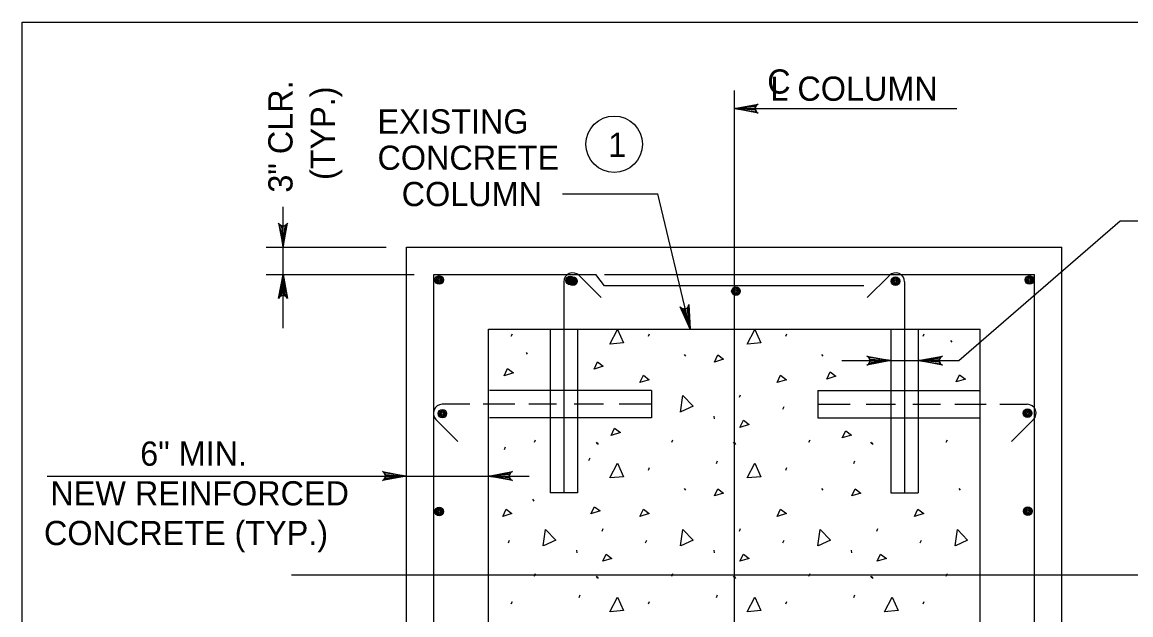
# Model space of a CAD drawing. Extents: x 646165 to 651486, y 296916 to 299292.
# Drawn here: x 650670.6 to 650808, y 298015.8 to 298089.3 of the extents above; entities that cross this region are included whole.
import ezdxf

# ---------------------------------------------------------------- set-up
doc = ezdxf.new("R2010")
doc.units = 0
for name, color, linetype in [('2', 7, 'Continuous'), ('50', 7, 'Continuous'), ('51', 7, 'Continuous'), ('52', 7, 'Continuous'), ('53', 7, 'Continuous'), ('54', 7, 'Continuous'), ('56', 7, 'Continuous')]:
    doc.layers.add(name, color=color, linetype=linetype)

msp = doc.modelspace()

# ---------------------------------------------------------------- linework, layer by layer
at = {"layer": '2'}
for p, q in [((650670.59, 297525.25), (650670.59, 298089.25)), ((650670.59, 298089.25), (651456.59, 298089.25))]:
    msp.add_line(p, q, dxfattribs=at)
at = {"layer": '50'}
for p, q in [((650758.84, 298080.79), (650758.84, 297974.65)), ((650703.98, 298020.74), (650812.55, 298020.74))]:
    msp.add_line(p, q, dxfattribs=at)
at = {"layer": '51'}
for p, q in [((650718.21, 297980.12), (650718.21, 298061.37)), ((650718.21, 298061.37), (650799.47, 298061.37)), ((650799.47, 297980.12), (650799.47, 298061.37)), ((650728.37, 297990.27), (650728.37, 298051.21)), ((650728.37, 298051.21), (650789.31, 298051.21)), ((650736.02, 298051.21), (650736.02, 298030.9)), ((650739.41, 298051.21), (650739.41, 298030.9)), ((650778.27, 298051.21), (650778.27, 298030.9)), ((650781.66, 298051.21), (650781.66, 298030.9)), ((650789.31, 297990.27), (650789.31, 298051.21)), ((650748.61, 298043.58), (650728.5, 298043.58)), ((650748.61, 298043.58), (650748.61, 298040.2)), ((650769.2, 298043.58), (650789.31, 298043.58)), ((650769.2, 298043.58), (650769.2, 298040.2)), ((650748.61, 298040.2), (650728.5, 298040.2)), ((650769.2, 298040.2), (650789.31, 298040.2)), ((650739.41, 298030.9), (650736.02, 298030.9)), ((650778.27, 298030.9), (650781.66, 298030.9))]:
    msp.add_line(p, q, dxfattribs=at)
at = {"layer": '52'}
for p, q in [((650758.84, 298078.54), (650786.45, 298078.54)), ((650737.55, 298067.96), (650749.37, 298067.96)), ((650753.37, 298051.21), (650749.37, 298067.96)), ((650702.93, 298051.32), (650702.93, 298066.38)), ((650786.68, 298047.3), (650806.7, 298064.64)), ((650806.7, 298064.64), (650812.07, 298064.64)), ((650700.85, 298061.37), (650715.69, 298061.37)), ((650700.85, 298057.99), (650719.17, 298057.99)), ((650772.17, 298047.3), (650786.68, 298047.3)), ((650673.7, 298032.99), (650733.41, 298032.99))]:
    msp.add_line(p, q, dxfattribs=at)
for points in [[(650758.84, 298078.54), (650761.82, 298079.1), (650761.59, 298078.94), (650761.47, 298078.74), (650761.44, 298078.54), (650761.47, 298078.34), (650761.59, 298078.14), (650761.82, 298077.98), (650758.84, 298078.54), (650761.59, 298078.14), (650761.47, 298078.34), (650758.84, 298078.54), (650761.44, 298078.54), (650761.47, 298078.74), (650758.84, 298078.54), (650761.59, 298078.94)], [(650702.93, 298061.37), (650703.49, 298064.35), (650703.33, 298064.12), (650703.13, 298064.01), (650702.93, 298063.97), (650702.73, 298064.01), (650702.53, 298064.12), (650702.37, 298064.35), (650702.93, 298061.37), (650702.53, 298064.12), (650702.73, 298064.01), (650702.93, 298061.37), (650702.93, 298063.97), (650703.13, 298064.01), (650702.93, 298061.37), (650703.33, 298064.12)], [(650702.93, 298057.99), (650703.49, 298055), (650703.33, 298055.23), (650703.13, 298055.35), (650702.93, 298055.39), (650702.73, 298055.35), (650702.53, 298055.23), (650702.37, 298055), (650702.93, 298057.99), (650702.53, 298055.23), (650702.73, 298055.35), (650702.93, 298057.99), (650702.93, 298055.39), (650703.13, 298055.35), (650702.93, 298057.99), (650703.33, 298055.23)], [(650753.37, 298051.21), (650752.13, 298053.99), (650752.34, 298053.8), (650752.56, 298053.73), (650752.77, 298053.74), (650752.95, 298053.82), (650753.12, 298053.98), (650753.22, 298054.25), (650753.37, 298051.21), (650753.12, 298053.98), (650752.95, 298053.82), (650753.37, 298051.21), (650752.77, 298053.74), (650752.56, 298053.73), (650753.37, 298051.21), (650752.34, 298053.8)], [(650778.27, 298047.3), (650775.29, 298046.74), (650775.52, 298046.9), (650775.64, 298047.1), (650775.67, 298047.3), (650775.64, 298047.5), (650775.52, 298047.7), (650775.29, 298047.86), (650778.27, 298047.3), (650775.52, 298047.7), (650775.64, 298047.5), (650778.27, 298047.3), (650775.67, 298047.3), (650775.64, 298047.1), (650778.27, 298047.3), (650775.52, 298046.9)], [(650781.66, 298047.3), (650784.64, 298047.86), (650784.41, 298047.7), (650784.29, 298047.5), (650784.26, 298047.3), (650784.29, 298047.1), (650784.41, 298046.9), (650784.64, 298046.74), (650781.66, 298047.3), (650784.41, 298046.9), (650784.29, 298047.1), (650781.66, 298047.3), (650784.26, 298047.3), (650784.29, 298047.5), (650781.66, 298047.3), (650784.41, 298047.7)], [(650718.21, 298032.99), (650715.23, 298032.43), (650715.46, 298032.59), (650715.58, 298032.79), (650715.61, 298032.99), (650715.58, 298033.19), (650715.46, 298033.39), (650715.23, 298033.55), (650718.21, 298032.99), (650715.46, 298033.39), (650715.58, 298033.19), (650718.21, 298032.99), (650715.61, 298032.99), (650715.58, 298032.79), (650718.21, 298032.99), (650715.46, 298032.59)], [(650728.37, 298032.99), (650731.35, 298033.55), (650731.12, 298033.39), (650731, 298033.19), (650730.97, 298032.99), (650731, 298032.79), (650731.12, 298032.59), (650731.35, 298032.43), (650728.37, 298032.99), (650731.12, 298032.59), (650731, 298032.79), (650728.37, 298032.99), (650730.97, 298032.99), (650731, 298033.19), (650728.37, 298032.99), (650731.12, 298033.39)]]:
    msp.add_lwpolyline(points, dxfattribs=at)
msp.add_circle((650743.96, 298074.12), 3.5, dxfattribs=at)
at = {"layer": '54'}
for p, q in [((650721.6, 297983.5), (650721.6, 298057.99)), ((650721.6, 298057.99), (650741.69, 298057.99)), ((650737.71, 298057.06), (650737.71, 298030.9)), ((650739.61, 298057.85), (650742.34, 298055.12)), ((650742.76, 298056.56), (650741.69, 298057.99)), ((650742.76, 298057.99), (650796.08, 298057.99)), ((650778.07, 298057.85), (650775.34, 298055.12)), ((650779.96, 298057.06), (650779.96, 298030.9)), ((650796.08, 297983.5), (650796.08, 298057.99)), ((650774.92, 298056.56), (650742.76, 298056.56)), ((650726.06, 298041.89), (650722.66, 298041.89)), ((650731.64, 298041.89), (650727.73, 298041.89)), ((650736.81, 298041.89), (650733.39, 298041.89)), ((650742.63, 298041.89), (650738.99, 298041.89)), ((650748.61, 298041.89), (650744.6, 298041.89)), ((650769.2, 298041.89), (650773.21, 298041.89)), ((650775.18, 298041.89), (650778.82, 298041.89)), ((650781, 298041.89), (650784.42, 298041.89)), ((650786.17, 298041.89), (650790.08, 298041.89)), ((650791.75, 298041.89), (650795.15, 298041.89)), ((650721.88, 298039.99), (650724.6, 298037.27)), ((650795.93, 298039.99), (650793.21, 298037.27))]:
    msp.add_line(p, q, dxfattribs=at)
for centre, radius in [((650722.27, 298057.3), 0.533), ((650722.27, 298057.3), 0.4), ((650722.27, 298057.3), 0.267), ((650722.27, 298057.3), 0.133), ((650738.52, 298057.24), 0.533), ((650738.52, 298057.24), 0.4), ((650738.52, 298057.24), 0.267), ((650738.86, 298057.16), 0.533), ((650738.52, 298057.24), 0.133), ((650738.86, 298057.16), 0.4), ((650738.86, 298057.16), 0.267), ((650738.86, 298057.16), 0.133), ((650778.82, 298057.16), 0.533), ((650778.82, 298057.16), 0.4), ((650778.82, 298057.16), 0.267), ((650778.82, 298057.16), 0.133), ((650795.43, 298057.3), 0.533), ((650795.43, 298057.3), 0.4), ((650795.43, 298057.3), 0.267), ((650795.43, 298057.3), 0.133), ((650759.06, 298055.92), 0.533), ((650759.06, 298055.92), 0.4), ((650759.06, 298055.92), 0.267), ((650759.06, 298055.92), 0.133), ((650722.67, 298040.73), 0.533), ((650722.67, 298040.73), 0.4), ((650722.67, 298040.73), 0.267), ((650722.67, 298040.73), 0.133), ((650795.21, 298040.8), 0.533), ((650795.21, 298040.8), 0.4), ((650795.21, 298040.8), 0.267), ((650795.21, 298040.8), 0.133), ((650722.27, 298028.59), 0.533), ((650722.27, 298028.59), 0.4), ((650722.27, 298028.59), 0.267), ((650722.27, 298028.59), 0.133), ((650795.25, 298028.65), 0.533), ((650795.25, 298028.65), 0.4), ((650795.25, 298028.65), 0.267), ((650795.25, 298028.65), 0.133)]:
    msp.add_circle(centre, radius, dxfattribs=at)
for centre, start, end in [((650738.83, 298057.06), 45, 180), ((650778.85, 298057.06), 0, 135), ((650722.66, 298040.78), 90, 225), ((650795.15, 298040.78), 315, 90)]:
    msp.add_arc(centre, 1.11, start, end, dxfattribs=at)
at = {"layer": '56'}
for p, q in [((650731.21, 298050.32), (650731.35, 298050.64)), ((650739.62, 298051.14), (650739.66, 298051.21)), ((650748.22, 298050.32), (650748.36, 298050.64)), ((650756.64, 298051.14), (650756.67, 298051.21)), ((650765.24, 298050.32), (650765.38, 298050.64)), ((650773.65, 298051.14), (650773.69, 298051.21)), ((650782.25, 298050.32), (650782.39, 298050.64)), ((650785.67, 298049.8), (650785.81, 298049.58)), ((650733.05, 298048.3), (650733.19, 298048.09)), ((650752.66, 298048.05), (650752.8, 298047.84)), ((650769.68, 298048.05), (650769.82, 298047.84)), ((650759.48, 298042.76), (650759.62, 298043.08)), ((650764.88, 298041.3), (650765.02, 298041.62)), ((650756.31, 298040.41), (650756.35, 298040.09)), ((650730.37, 298036.28), (650730.51, 298036.6)), ((650734.08, 298037.18), (650734.22, 298037.5)), ((650741.72, 298037.18), (650741.86, 298036.97)), ((650741.86, 298037.1), (650742, 298036.89)), ((650751.1, 298037.18), (650751.24, 298037.5)), ((650758.73, 298037.18), (650758.88, 298036.97)), ((650758.88, 298037.1), (650759.02, 298036.89)), ((650768.11, 298037.18), (650768.25, 298037.5)), ((650775.75, 298037.18), (650775.89, 298036.97)), ((650775.89, 298037.1), (650776.03, 298036.89)), ((650785.13, 298037.18), (650785.27, 298037.5)), ((650740.84, 298034.92), (650740.98, 298035.24)), ((650748.22, 298033.73), (650748.36, 298034.05)), ((650756.64, 298034.55), (650756.78, 298034.87)), ((650765.24, 298033.73), (650765.38, 298034.05)), ((650773.65, 298034.55), (650773.8, 298034.87)), ((650752.66, 298031.46), (650752.8, 298031.24)), ((650769.68, 298031.46), (650769.82, 298031.24)), ((650786.69, 298031.46), (650786.83, 298031.24)), ((650733.85, 298030.12), (650733.99, 298029.9)), ((650742.47, 298026.16), (650742.61, 298026.48)), ((650759.48, 298026.16), (650759.62, 298026.48)), ((650776.5, 298026.16), (650776.64, 298026.48)), ((650730.85, 298024.71), (650730.99, 298025.03)), ((650747.86, 298024.71), (650748.01, 298025.03)), ((650764.88, 298024.71), (650765.02, 298025.03)), ((650781.9, 298024.71), (650782.04, 298025.03)), ((650739.3, 298023.82), (650739.33, 298023.5)), ((650756.31, 298023.82), (650756.35, 298023.5)), ((650773.33, 298023.82), (650773.36, 298023.5)), ((650734.08, 298020.59), (650734.22, 298020.91)), ((650741.72, 298020.59), (650741.86, 298020.37)), ((650741.86, 298020.51), (650742, 298020.29)), ((650751.1, 298020.59), (650751.24, 298020.91)), ((650758.73, 298020.59), (650758.88, 298020.37)), ((650758.88, 298020.51), (650759.02, 298020.29)), ((650768.11, 298020.59), (650768.25, 298020.91)), ((650775.75, 298020.59), (650775.89, 298020.37)), ((650775.89, 298020.51), (650776.03, 298020.29)), ((650785.13, 298020.59), (650785.27, 298020.91)), ((650731.21, 298017.14), (650731.35, 298017.46)), ((650739.62, 298017.95), (650739.77, 298018.27)), ((650748.22, 298017.14), (650748.36, 298017.46)), ((650756.64, 298017.95), (650756.78, 298018.27)), ((650765.24, 298017.14), (650765.38, 298017.46)), ((650773.65, 298017.95), (650773.8, 298018.27)), ((650782.25, 298017.14), (650782.39, 298017.46))]:
    msp.add_line(p, q, dxfattribs=at)
for points in [[(650743.42, 298049.36), (650744.38, 298051.18), (650745.13, 298049.51), (650743.46, 298049.36)], [(650760.44, 298049.36), (650761.4, 298051.18), (650762.14, 298049.51), (650760.48, 298049.36)], [(650756.39, 298047.13), (650756.82, 298048.01), (650757.53, 298047.48), (650756.39, 298047.13)], [(650730.33, 298045.42), (650730.75, 298046.31), (650731.47, 298045.78), (650730.33, 298045.42)], [(650741.47, 298046.25), (650741.89, 298047.14), (650742.6, 298046.6), (650741.47, 298046.25)], [(650747.16, 298044.59), (650747.59, 298045.48), (650748.3, 298044.94), (650747.16, 298044.59)], [(650764.18, 298044.59), (650764.6, 298045.48), (650765.31, 298044.94), (650764.18, 298044.59)], [(650770.31, 298045.02), (650770.74, 298045.9), (650771.45, 298045.37), (650770.31, 298045.02)], [(650786.36, 298044.66), (650786.78, 298045.55), (650787.5, 298045.01), (650786.36, 298044.66)], [(650752.19, 298040.93), (650752.47, 298042.96), (650753.74, 298041.65), (650752.22, 298040.95)], [(650759.55, 298039.03), (650759.98, 298039.92), (650760.69, 298039.38), (650759.55, 298039.03)], [(650743.59, 298038.04), (650744.02, 298038.93), (650744.73, 298038.4), (650743.59, 298038.04)], [(650772.24, 298037.72), (650772.66, 298038.61), (650773.37, 298038.07), (650772.24, 298037.72)], [(650743.42, 298032.77), (650744.38, 298034.58), (650745.13, 298032.91), (650743.46, 298032.77)], [(650760.44, 298032.77), (650761.4, 298034.58), (650762.14, 298032.91), (650760.48, 298032.77)], [(650756.39, 298030.53), (650756.82, 298031.42), (650757.53, 298030.89), (650756.39, 298030.53)], [(650773.41, 298030.53), (650773.83, 298031.42), (650774.54, 298030.89), (650773.41, 298030.53)], [(650730.15, 298027.99), (650730.57, 298028.88), (650731.28, 298028.35), (650730.15, 298027.99)], [(650741.09, 298028.32), (650741.52, 298029.2), (650742.23, 298028.67), (650741.09, 298028.32)], [(650747.16, 298027.99), (650747.59, 298028.88), (650748.3, 298028.35), (650747.16, 298027.99)], [(650764.18, 298027.99), (650764.6, 298028.88), (650765.31, 298028.35), (650764.18, 298027.99)], [(650781.19, 298027.99), (650781.62, 298028.88), (650782.33, 298028.35), (650781.19, 298027.99)], [(650735.17, 298024.34), (650735.45, 298026.37), (650736.72, 298025.06), (650735.2, 298024.35)], [(650752.19, 298024.34), (650752.47, 298026.37), (650753.74, 298025.06), (650752.22, 298024.35)], [(650769.2, 298024.34), (650769.48, 298026.37), (650770.76, 298025.06), (650769.23, 298024.35)], [(650786.22, 298024.34), (650786.5, 298026.37), (650787.77, 298025.06), (650786.25, 298024.35)], [(650742.54, 298022.43), (650742.96, 298023.32), (650743.67, 298022.79), (650742.54, 298022.43)], [(650759.55, 298022.43), (650759.98, 298023.32), (650760.69, 298022.79), (650759.55, 298022.43)], [(650776.57, 298022.43), (650776.99, 298023.32), (650777.7, 298022.79), (650776.57, 298022.43)], [(650743.42, 298016.18), (650744.38, 298017.99), (650745.13, 298016.32), (650743.46, 298016.18)], [(650760.44, 298016.18), (650761.4, 298017.99), (650762.14, 298016.32), (650760.48, 298016.18)], [(650777.46, 298016.18), (650778.41, 298017.99), (650779.16, 298016.32), (650777.49, 298016.18)]]:
    msp.add_lwpolyline(points, dxfattribs=at)

# ---------------------------------------------------------------- texts
at = {"layer": '53'}
for s, p in [('C', (650762.94, 298080.4)), ('L COLUMN', (650763.33, 298079.51)), ('EXISTING', (650714.63, 298075.45)), ('1', (650743.21, 298072.55)), ('CONCRETE', (650714.63, 298070.95)), ('COLUMN', (650717.63, 298066.45)), ('6" MIN.', (650685.22, 298034.28)), ('NEW REINFORCED', (650674.09, 298029.36)), ('CONCRETE (TYP.)', (650673.29, 298024.44))]:
    msp.add_text(s, height=3, dxfattribs=at).set_placement(p)
for s, p in [('3" CLR.', (650704.1, 298068.12)), ('(TYP.)', (650709.35, 298069.69))]:
    msp.add_text(s, height=3, rotation=90, dxfattribs=at).set_placement(p)

doc.saveas('drawing.dxf')
